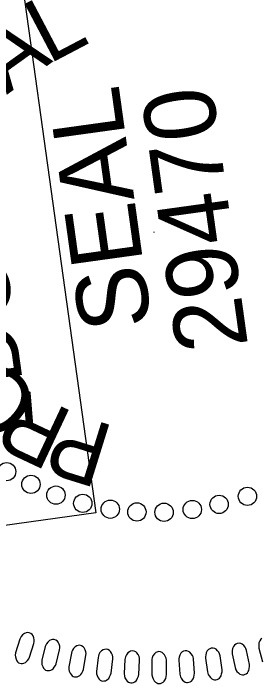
# Model space of a CAD drawing. Extents: x 477151 to 478666, y 496366 to 498184.
# Drawn here: x 477483.9 to 477505.6, y 497845.7 to 497904.4 of the extents above; entities that cross this region are included whole.
import ezdxf

# ---------------------------------------------------------------- set-up
doc = ezdxf.new("R2010")
doc.units = 0
doc.layers.add('Sheet PE Seal Cell', color=7, linetype='Continuous')
doc.layers.add('Sheet Sticker Incomplete CELL', color=7, linetype='Continuous')

msp = doc.modelspace()

# ---------------------------------------------------------------- linework, layer by layer
at = {"layer": 'Sheet PE Seal Cell'}
msp.add_line((477496.144, 497885.226), (477496.19, 497885.232), dxfattribs=at)
for points in [[(477484.413, 497849.589), (477484.049, 497848.417), (477484.019, 497848.197), (477484.027, 497848.048), (477484.084, 497847.853), (477484.144, 497847.719), (477484.227, 497847.61), (477484.315, 497847.54), (477484.417, 497847.488), (477484.53, 497847.474), (477484.653, 497847.467), (477484.77, 497847.493), (477484.9, 497847.557), (477484.98, 497847.615), (477485.089, 497847.738), (477485.2, 497847.892), (477485.269, 497848.037), (477485.65, 497849.236), (477485.678, 497849.404), (477485.677, 497849.55), (477485.639, 497849.729), (477485.573, 497849.896), (477485.504, 497850.001), (477485.372, 497850.105), (477485.235, 497850.168), (477485.081, 497850.174), (477484.966, 497850.158), (477484.815, 497850.101), (477484.65, 497849.975), (477484.533, 497849.823), (477484.466, 497849.708)], [(477486.641, 497848.95), (477486.351, 497847.759), (477486.335, 497847.537), (477486.352, 497847.389), (477486.421, 497847.197), (477486.49, 497847.068), (477486.58, 497846.964), (477486.673, 497846.9), (477486.777, 497846.854), (477486.89, 497846.847), (477487.014, 497846.848), (477487.129, 497846.881), (477487.254, 497846.953), (477487.332, 497847.016), (477487.433, 497847.146), (477487.533, 497847.306), (477487.593, 497847.456), (477487.897, 497848.675), (477487.915, 497848.845), (477487.905, 497848.991), (477487.856, 497849.167), (477487.78, 497849.33), (477487.704, 497849.43), (477487.566, 497849.526), (477487.426, 497849.58), (477487.271, 497849.577), (477487.157, 497849.553), (477487.01, 497849.487), (477486.854, 497849.35), (477486.746, 497849.191), (477486.686, 497849.072)], [(477488.93, 497848.385), (477488.715, 497847.177), (477488.714, 497846.955), (477488.74, 497846.807), (477488.821, 497846.621), (477488.898, 497846.496), (477488.994, 497846.398), (477489.09, 497846.341), (477489.197, 497846.301), (477489.311, 497846.301), (477489.434, 497846.31), (477489.547, 497846.35), (477489.668, 497846.43), (477489.741, 497846.498), (477489.834, 497846.634), (477489.923, 497846.799), (477489.974, 497846.953), (477490.202, 497848.189), (477490.209, 497848.36), (477490.189, 497848.505), (477490.129, 497848.678), (477490.043, 497848.834), (477489.961, 497848.931), (477489.818, 497849.017), (477489.674, 497849.063), (477489.519, 497849.049), (477489.408, 497849.019), (477489.265, 497848.943), (477489.118, 497848.797), (477489.02, 497848.632), (477488.968, 497848.509)], [(477491.261, 497847.998), (477491.123, 497846.779), (477491.135, 497846.557), (477491.171, 497846.412), (477491.263, 497846.231), (477491.347, 497846.111), (477491.45, 497846.018), (477491.549, 497845.968), (477491.659, 497845.935), (477491.772, 497845.942), (477491.895, 497845.958), (477492.005, 497846.006), (477492.12, 497846.093), (477492.189, 497846.165), (477492.273, 497846.307), (477492.352, 497846.478), (477492.393, 497846.634), (477492.542, 497847.882), (477492.539, 497848.053), (477492.51, 497848.197), (477492.439, 497848.365), (477492.344, 497848.517), (477492.256, 497848.607), (477492.107, 497848.685), (477491.961, 497848.721), (477491.808, 497848.698), (477491.698, 497848.661), (477491.56, 497848.576), (477491.423, 497848.421), (477491.335, 497848.25), (477491.291, 497848.124)], [(477500.663, 497847.945), (477500.832, 497846.73), (477500.9, 497846.518), (477500.97, 497846.387), (477501.104, 497846.234), (477501.216, 497846.139), (477501.338, 497846.076), (477501.447, 497846.051), (477501.561, 497846.046), (477501.669, 497846.081), (477501.783, 497846.127), (477501.879, 497846.2), (477501.969, 497846.314), (477502.017, 497846.401), (477502.063, 497846.559), (477502.098, 497846.745), (477502.098, 497846.906), (477501.933, 497848.152), (477501.887, 497848.316), (477501.823, 497848.449), (477501.712, 497848.594), (477501.582, 497848.717), (477501.475, 497848.783), (477501.311, 497848.821), (477501.16, 497848.82), (477501.018, 497848.759), (477500.921, 497848.696), (477500.809, 497848.58), (477500.714, 497848.395), (477500.672, 497848.208), (477500.66, 497848.075)], [(477502.991, 497848.322), (477503.235, 497847.12), (477503.316, 497846.913), (477503.395, 497846.786), (477503.539, 497846.642), (477503.656, 497846.553), (477503.782, 497846.498), (477503.892, 497846.48), (477504.006, 497846.483), (477504.112, 497846.525), (477504.223, 497846.579), (477504.314, 497846.657), (477504.396, 497846.776), (477504.439, 497846.866), (477504.475, 497847.026), (477504.498, 497847.214), (477504.488, 497847.374), (477504.245, 497848.608), (477504.189, 497848.77), (477504.117, 497848.897), (477503.997, 497849.035), (477503.86, 497849.15), (477503.749, 497849.209), (477503.583, 497849.237), (477503.432, 497849.226), (477503.294, 497849.157), (477503.201, 497849.087), (477503.097, 497848.964), (477503.013, 497848.775), (477502.983, 497848.585), (477502.98, 497848.452)], [(477493.606, 497847.808), (477493.544, 497846.583), (477493.57, 497846.362), (477493.614, 497846.219), (477493.719, 497846.044), (477493.81, 497845.93), (477493.918, 497845.845), (477494.02, 497845.8), (477494.131, 497845.774), (477494.244, 497845.789), (477494.365, 497845.812), (477494.473, 497845.866), (477494.582, 497845.961), (477494.646, 497846.038), (477494.721, 497846.184), (477494.79, 497846.36), (477494.82, 497846.518), (477494.892, 497847.773), (477494.877, 497847.944), (477494.839, 497848.085), (477494.758, 497848.249), (477494.653, 497848.394), (477494.56, 497848.479), (477494.406, 497848.546), (477494.258, 497848.574), (477494.106, 497848.542), (477494, 497848.497), (477493.867, 497848.404), (477493.739, 497848.241), (477493.663, 497848.064), (477493.627, 497847.936)], [(477495.956, 497847.711), (477495.971, 497846.484), (477496.011, 497846.265), (477496.065, 497846.126), (477496.179, 497845.958), (477496.277, 497845.849), (477496.391, 497845.771), (477496.496, 497845.732), (477496.608, 497845.714), (477496.72, 497845.735), (477496.839, 497845.767), (477496.943, 497845.828), (477497.046, 497845.929), (477497.105, 497846.009), (477497.171, 497846.16), (477497.228, 497846.34), (477497.249, 497846.5), (477497.241, 497847.756), (477497.216, 497847.926), (477497.17, 497848.064), (477497.079, 497848.223), (477496.964, 497848.361), (477496.866, 497848.44), (477496.708, 497848.498), (477496.558, 497848.516), (477496.41, 497848.474), (477496.305, 497848.423), (477496.18, 497848.322), (477496.062, 497848.151), (477495.997, 497847.97), (477495.969, 497847.84)], [(477498.317, 497847.75), (477498.409, 497846.527), (477498.463, 497846.31), (477498.525, 497846.175), (477498.649, 497846.014), (477498.755, 497845.912), (477498.873, 497845.841), (477498.98, 497845.809), (477499.093, 497845.798), (477499.203, 497845.827), (477499.321, 497845.865), (477499.42, 497845.932), (477499.517, 497846.04), (477499.571, 497846.124), (477499.627, 497846.278), (477499.673, 497846.462), (477499.684, 497846.622), (477499.597, 497847.876), (477499.562, 497848.044), (477499.506, 497848.179), (477499.405, 497848.332), (477499.283, 497848.463), (477499.18, 497848.535), (477499.019, 497848.583), (477498.868, 497848.591), (477498.722, 497848.54), (477498.621, 497848.483), (477498.502, 497848.374), (477498.396, 497848.196), (477498.342, 497848.012), (477498.322, 497847.88)]]:
    msp.add_lwpolyline(points, close=True, dxfattribs=at)
msp.add_lwpolyline([(477505.577, 497849.666), (477505.489, 497849.59), (477505.392, 497849.461), (477505.321, 497849.266), (477505.303, 497849.075), (477505.308, 497848.942), (477505.327, 497848.813), (477505.646, 497847.629)], dxfattribs=at)
for centre in [(477483.265, 497864.258), (477485.39, 497863.146), (477487.573, 497862.203), (477504.323, 497862.1), (477489.925, 497861.484), (477501.847, 497861.394), (477492.328, 497860.974), (477499.496, 497860.947), (477494.654, 497860.734), (477497.031, 497860.702)]:
    msp.add_circle(centre, 0.801, dxfattribs=at)
at = {"layer": 'Sheet Sticker Incomplete CELL'}
msp.add_lwpolyline([(477491.078, 497860.666), (477467.803, 497857.427), (477447.541, 498003.024), (477470.816, 498006.263)], close=True, dxfattribs=at)

# ---------------------------------------------------------------- texts
at = {"layer": 'Sheet PE Seal Cell'}
for s, height, rotation, p in [('L', 5.669, 27.75354, (477486.932, 497899.875)), ('A', 5.669, 35.69333, (477483.268, 497897.221)), ('SEAL', 6.2363, 97.90404, (477495.972, 497877.082)), ('29470', 6.2363, 97.90404, (477504.383, 497875.252)), ('O', 5.669, 138.9107, (477486.498, 497870.745)), ('R', 5.669, 154.79029, (477489.256, 497869.398)), ('P', 5.669, 162.73009, (477492.818, 497868.191))]:
    msp.add_text(s, height=height, rotation=rotation, dxfattribs=at).set_placement(p)
at = {"layer": 'Sheet Sticker Incomplete CELL'}
msp.add_text('DO NOT USE FOR R/W ACQUISITION', height=5.76, rotation=97.92268, dxfattribs=at).set_placement((477484.692, 497872.095))

doc.saveas('drawing.dxf')
